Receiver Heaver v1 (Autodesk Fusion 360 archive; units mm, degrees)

design "Receiver Heaver" references "91855A480_18-8 STAINLESS STEEL CAP NUT", "90107A029_TYPE 316 STAINLESS STEEL FLAT WASHER (1)", "95412A736_18-8 STAINLESS STEEL THREADED ROD", "92141A033_TYPE 18-8 STAINLESS STEEL FLAT WASHER", "90876A450_STEEL AND IRON WING NUTS", "6079K140_STEEL KNURLED-RIM KNOB", "91855A520_18-8 STAINLESS STEEL CAP NUT"
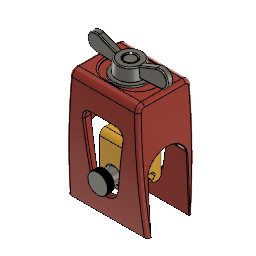
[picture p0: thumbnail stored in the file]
sketch "1913 Profile" plane through (0, 0, 0) normal (1, 0, 0) x axis (0, 1, 0)
  line L1 (-8.2514, 0) -> (-1.27, 0)
  line L2 (-10.5764, -2.2198) -> (-8.431, -0.0744)
  line L3 (-10.6426, -3.9497) -> (-10.6426, -2.286)
  line L4 (-8.0759, -6.5164) -> (-10.5764, -4.0159)
  line L5 (-7.874, -6.7193) -> (-7.874, -6.7183)
  line L6 (-12.6963, -9.2603) -> (-10.413, -9.2593)
  line L7 (-9.7763, 28.3845) -> (-9.7763, 16.5028)
  line L8 (0, 28.6385) -> (-9.5223, 28.6385)
  line L9 (0, 34.9885) -> (0, 28.6385)
  line L10 (-11.4416, 34.9885) -> (0, 34.9885)
  line L11 (-16.5079, -5.4518) -> (-16.5216, 29.9065)
  line L12 (-0.635, 6.9855) -> (-0.635, 0.635)
  line L13 (11.4417, 34.9885) -> (0, 34.9885)
  line L14 (16.508, -5.4518) -> (16.5217, 29.9065)
  line L15 (12.6964, -9.2603) -> (10.413, -9.2593)
  line L16 (8.076, -6.5164) -> (10.5765, -4.0159)
  line L17 (10.5765, -2.2198) -> (8.4311, -0.0744)
  line L18 (8.2515, 0) -> (1.2701, 0)
  line L19 (0.6351, 6.9855) -> (0.6351, 0.635)
  line L20 (9.7764, 28.3845) -> (9.7764, 16.5028)
  line L21 (0, 28.6385) -> (9.5224, 28.6385)
  arc A1 centre (-0.8863, 16.5028) radius 8.89 clockwise from (-1.2444, 7.62) to (-9.7763, 16.5028)
  arc A2 centre (-9.5223, 28.3845) radius 0.254 clockwise from (-9.7763, 28.3845) to (-9.5223, 28.6385)
  arc A3 centre (-10.414, -6.7193) radius 2.54 clockwise from (-7.8953, -7.0474) to (-10.413, -9.2593)
  arc A4 centre (-8.525, -6.9654) radius 0.635 clockwise from (-8.0759, -6.5164) to (-7.8953, -7.0474)
  arc A5 centre (-9.6784, -3.1179) radius 1.27 clockwise from (-10.5764, -4.0159) to (-10.5764, -2.2198)
  arc A6 centre (-1.27, 0.635) radius 0.635 clockwise from (-0.635, 0.635) to (-1.27, 0)
  arc A7 centre (-12.6979, -5.4503) radius 3.81 clockwise from (-12.6963, -9.2603) to (-16.5079, -5.4518)
  arc A8 centre (-11.4416, 29.9085) radius 5.08 clockwise from (-16.5216, 29.9065) to (-11.4416, 34.9885)
  arc A9 centre (-8.2514, -0.254) radius 0.254 clockwise from (-8.431, -0.0744) to (-8.2514, 0)
  arc A10 centre (-1.27, 6.9855) radius 0.635 clockwise from (-1.2444, 7.62) to (-0.635, 6.9855)
  arc A11 centre (11.4417, 29.9085) radius 5.08 clockwise from (11.4417, 34.9885) to (16.5217, 29.9065)
  arc A12 centre (12.698, -5.4503) radius 3.81 clockwise from (16.508, -5.4518) to (12.6964, -9.2603)
  arc A13 centre (10.4141, -6.7193) radius 2.54 clockwise from (10.413, -9.2593) to (7.8953, -7.0474)
  arc A14 centre (8.525, -6.9654) radius 0.635 clockwise from (7.8953, -7.0474) to (8.076, -6.5164)
  arc A15 centre (9.6785, -3.1179) radius 1.27 clockwise from (10.5765, -2.2198) to (10.5765, -4.0159)
  arc A16 centre (8.2515, -0.254) radius 0.254 clockwise from (8.2515, 0) to (8.4311, -0.0744)
  arc A17 centre (1.2701, 0.635) radius 0.635 clockwise from (1.2701, 0) to (0.6351, 0.635)
  arc A18 centre (1.2701, 6.9855) radius 0.635 clockwise from (0.6351, 6.9855) to (1.2445, 7.62)
  arc A19 centre (0.8864, 16.5028) radius 8.89 clockwise from (9.7764, 16.5028) to (1.2445, 7.62)
  arc A20 centre (9.5224, 28.3845) radius 0.254 clockwise from (9.5224, 28.6385) to (9.7764, 28.3845)
  point P8 (-9.7763, 9.525)
  point P5 (-7.874, -9.2583)
  point P7 (-9.2583, -5.334)
  point P6 (-9.4996, -1.143)
  point P2 (-10.6426, -2.286)
  point P3 (-10.6426, -3.9497)
  point P17 (-1.0952, 0)
  point P13 (-11.4427, 34.9885)
  point P9 (0, 28.6385)
  point P70 (0, 28.6385)
  point P10 (-9.7763, 16.5028)
  point P67 (9.7764, 16.5028)
  point P12 (0, 34.9885)
  point P42 (0, 34.9885)
  point P14 (-9.5223, 28.6385)
  point P69 (9.5224, 28.6385)
  point P15 (-9.7763, 28.3845)
  point P68 (9.7764, 28.3845)
  point P18 (-10.413, -9.2593)
  point P49 (10.413, -9.2593)
  point P21 (-8.0759, -6.5164)
  point P53 (8.076, -6.5164)
  point P22 (-7.8953, -7.0474)
  point P51 (7.8953, -7.0474)
  point P24 (-10.5764, -2.2198)
  point P56 (10.5765, -2.2198)
  point P25 (-10.5764, -4.0159)
  point P54 (10.5765, -4.0159)
  point P27 (-1.27, 0)
  point P60 (1.2701, 0)
  point P28 (-0.635, 0.635)
  point P62 (0.6351, 0.635)
  point P30 (-16.5079, -5.4518)
  point P46 (16.508, -5.4518)
  point P31 (-12.6963, -9.2603)
  point P48 (12.6964, -9.2603)
  point P33 (-11.4416, 34.9885)
  point P43 (11.4417, 34.9885)
  point P34 (-16.5216, 29.9065)
  point P45 (16.5217, 29.9065)
  point P36 (-8.2514, 0)
  point P59 (8.2515, 0)
  point P37 (-8.431, -0.0744)
  point P57 (8.4311, -0.0744)
  point P39 (-0.635, 6.9855)
  point P63 (0.6351, 6.9855)
  point P40 (-1.2444, 7.62)
  point P65 (1.2445, 7.62)
  point P1 (0, 0)
  point P4 (-7.874, -6.7183)
  horizontal L1
  vertical L3
  parallel L3 L5
  perpendicular L7 L8
  coincident P8 L7
  tangent L7 A1
  perpendicular L8 L9
  perpendicular L9 L10
  tangent L8 A2
  tangent L7 A2
  coincident P5 L6
  coincident P5 L5
  tangent L6 A3
  tangent L5 A3
  coincident L4 P7
  tangent L4 A4
  tangent A3 A4
  coincident L2 P6
  coincident P2 L2
  coincident P3 L4
  tangent L2 A5
  tangent L4 A5
  coincident L1 P17
  tangent L1 A6
  tangent L11 A7
  tangent L6 A7
  coincident L10 P13
  tangent L10 A8
  tangent L11 A8
  tangent L1 A9
  tangent L2 A9
  vertical L12
  tangent A1 A10
  tangent L12 A10
  symmetric P9 L9 P70
  symmetric P10 L9 P67
  symmetric A1 L9 A19
  symmetric P12 L9 P42
  symmetric L9 P14 P69
  symmetric L9 P15 P68
  symmetric L9 A2 A20
  symmetric L9 P18 P49
  symmetric L9 A3 A13
  symmetric L9 P21 P53
  symmetric L9 P22 P51
  symmetric L9 A4 A14
  symmetric L9 P24 P56
  symmetric L9 P25 P54
  symmetric L9 A5 A15
  symmetric L9 P27 P60
  symmetric L9 P28 P62
  symmetric L9 A6 A17
  symmetric L9 P30 P46
  symmetric L9 P31 P48
  symmetric L9 A7 A12
  symmetric L9 P33 P43
  symmetric L9 P34 P45
  symmetric L9 A8 A11
  symmetric L9 P36 P59
  symmetric L9 P37 P57
  symmetric L9 A9 A16
  symmetric L9 P39 P63
  symmetric L9 P40 P65
  symmetric L9 A10 A18
  dimension "d9" distance P1 L3 = 10.6426 (= "( 0.838 / 2 ) * 1 in")
  dimension "d10" angle L2 L3 = 135
  dimension "d11" angle L3 L4 = 135
  dimension "d12" distance P1 L5 = 7.874 (= "( 0.620 / 2 ) * 1 in")
  dimension "d13" distance P6 P7 = 4.191
  dimension "d14" distance P1 P6 = 9.4996 (= "( 0.748 / 2 ) * 1 in")
  dimension "d15" distance P4 P5 = 2.54
  dimension "d20" radius A1 = 8.89
  dimension "d21" distance P9 P12 = 6.35
  dimension "d23" radius A2 = 0.254
  dimension "d30" radius A4 = 0.635
  dimension "d31" radius A5 = 1.27
  dimension "d32" radius A6 = 0.635
  dimension "d34" distance P12 P13 = 11.4427
  dimension "d36" distance P1 L11 = 16.51 (= "( 1.3 / 2 ) * 1 in")
  dimension "d37" radius A7 = 3.81
  dimension "d38" radius A8 = 5.08
  dimension "d39" radius A9 = 0.254
  dimension "d40" radius A10 = 0.635
  dimension "d41" distance P1 L12 = 0.635
  dimension "d50" distance L1 P40 = 7.62
  dimension "d51" distance L8 P40 = 21.0185 (= "( 13 / 16 ) * 1 in + 0.015 in")
canvas "Canvas1"
extrude "Extrude1" new body sketch "1913 Profile" profile of L1 L2 L4 L6 L7 L8 A1 L9 L10 A2 A3 A4 A5 A6 L11 A7 A8 A9 L12 A10 L13 A11 L14 A12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 distance 12.7 bodies "1913 Adapter"
sketch "1913 Top Holes" plane through (0, 0, 34.9885) normal (0, 0, 1) x axis (-1, 0, 0)
  line L1 (-12.7, 11.4416) -> (12.7, 11.4416)
  line L2 (-12.7, -11.4417) -> (-12.7, 11.4416)
  line L3 (12.7, -11.4417) -> (-12.7, -11.4417)
  line L4 (12.7, 11.4416) -> (12.7, -11.4417)
  circle C1 centre (0, 0) radius 6.7945
  circle C2 centre (0, 0) radius 13.97
  point P1 (0, 0)
  point P6 (0, 0)
  point P7 (0, 0)
  coincident P1 P6
  coincident P1 P7
  dimension "d44" diameter C1 = 13.589
  dimension "d45" diameter C2 = 27.94
extrude "Extrude2" cut sketch "1913 Top Holes" profile of C1 against normal blind 16.51
sketch "Through hole for 1913" plane through (0, -0.635, 0) normal (0, 1, 0) x axis (-1, 0, 0)
  line L1 (-12.7, 6.9855) -> (12.7, 6.9855)
  line L2 (-12.7, 0.635) -> (-12.7, 6.9855)
  line L3 (12.7, 0.635) -> (-12.7, 0.635)
  line L4 (12.7, 6.9855) -> (12.7, 0.635)
  circle C1 centre (0, 3.81) radius 3.6195
  dimension "d52" diameter C1 = 7.239
extrude "Extrude4" cut sketch "Through hole for 1913" profile of L1 L3 C1 distance 50.8
sketch "Sketch7" plane through (0, -16.51, -0.0064) normal (0, -1, -0.0004) x axis (1, 0, 0)
  line L1 (12.7, -5.4454) -> (-12.7, -5.4454)
  line L2 (12.7, 29.9129) -> (12.7, -5.4454)
  line L3 (-12.7, 29.9129) -> (12.7, 29.9129)
  line L4 (-12.7, -5.4454) -> (-12.7, 29.9129)
  closed curve K1 centre (0, 3.8164)
  circle C1 centre (0, 3.8164) radius 8.0645
  concentric K1 C1
  dimension "d55" diameter C1 = 16.129
extrude "Extrude6" cut sketch "Sketch7" profile of K1 C1 against normal blind 2.54
extrude "Extrude5" cut sketch "Sketch7" profile of K1 C1 against normal blind 1.27
sketch "Through hole nut" plane through (0, 16.5101, -0.0064) normal (0, 1, -0.0004) x axis (-1, 0, 0)
  line L1 (-12.7, 29.9129) -> (12.7, 29.9129)
  line L2 (-12.7, -5.4454) -> (-12.7, 29.9129)
  line L3 (12.7, -5.4454) -> (-12.7, -5.4454)
  line L4 (12.7, 29.9129) -> (12.7, -5.4454)
  line L5 (-6.5625, 3.81) -> (-3.2812, 9.4932)
  line L6 (-3.2812, -1.8733) -> (-6.5625, 3.81)
  line L7 (3.2812, -1.8733) -> (-3.2812, -1.8733)
  line L8 (6.5625, 3.81) -> (3.2812, -1.8733)
  line L9 (3.2812, 9.4932) -> (6.5625, 3.81)
  line L10 (-3.2812, 9.4932) -> (3.2812, 9.4932)
  point P6 (0, 3.81)
  point P7 (0, 3.81)
  point P14 (0, 3.81)
  coincident P6 P7
  coincident P7 P14
  dimension "d87" distance P14 L10 = 5.6832 (= "( ( 7 / 16 / 2 ) + 0.005 ) * 1 in")
extrude "Extrude8" cut sketch "Through hole nut" profile of L5 L6 L7 L8 L9 L10 against normal blind 3.7703 (magnitude of "( -19 / 32 / 4 ) * 1 in")
component_insert "Component Insert2"
joint "Assemble3" OffsetX 0 OffsetY 0 OffsetZ 0 AngleZ 0 alignAngle 0 alignOffsetX 0 alignOffsetY 0 alignOffsetZ 0
component_insert "Component Insert3"
joint "Assemble4" OffsetX 0 OffsetY 0 OffsetZ 0 AngleZ 0 OffsetX 0 OffsetY 0 OffsetZ 0 AngleZ 0 alignAngle 0 alignOffsetX 0 alignOffsetY 0 alignOffsetZ 0
component_insert "Component Insert4"
joint "Assemble5" OffsetX 0 OffsetY 0 OffsetZ 0 AngleZ 0 alignAngle -30 alignOffsetX 0 alignOffsetY 0 alignOffsetZ 0
component_insert "Component Insert6"
joint "Assemble6" OffsetX 0 OffsetY 0 OffsetZ 0 AngleZ 0 alignAngle -30 alignOffsetX 0 alignOffsetY 0 alignOffsetZ 0
component_insert "Component Insert7"
joint "Assemble7" OffsetX 0 OffsetY 0 OffsetZ 0 AngleZ 0 OffsetX 0 OffsetY 0 OffsetZ 0 AngleZ 0 alignAngle 180 alignOffsetX 0 alignOffsetY 0 alignOffsetZ 0
component_insert "Component Insert8"
component_insert "Component Insert9"
component_from_bodies "Body->Comp1"
sketch "Major part" plane through (0, 0, 0) normal (1, 0, 0) x axis (0, 1, 0)
  line L1 (-21.59, 0) -> (-17.78, 0)
  line L2 (-19.33, 107.95) -> (0, 107.95)
  line L3 (0, 95.25) -> (0, 107.95)
  line L4 (-2.941, 95.25) -> (0, 95.25)
  line L5 (19.33, 107.95) -> (0, 107.95)
  line L6 (21.59, 0) -> (17.78, 0)
  line L7 (2.941, 95.25) -> (0, 95.25)
  circle C1 centre (0, 0) radius 17.145
  arc A1 centre (608.8529, 76.2932) radius 635.0425 clockwise from (-21.59, 0) to (-25.6748, 101.8556)
  arc A2 centre (3834.7614, 59.3271) radius 3852.9981 clockwise from (-17.78, 0) to (-18.1808, 80.0921)
  arc A3 centre (-2.941, 80.01) radius 15.24 clockwise from (-18.1808, 80.0921) to (-2.941, 95.25)
  arc A4 centre (-19.33, 101.6) radius 6.35 clockwise from (-25.6748, 101.8556) to (-19.33, 107.95)
  arc A5 centre (19.33, 101.6) radius 6.35 clockwise from (19.33, 107.95) to (25.6748, 101.8556)
  arc A6 centre (-608.8529, 76.2932) radius 635.0425 clockwise from (25.6748, 101.8556) to (21.59, 0)
  arc A7 centre (-3834.7614, 59.3271) radius 3852.9981 clockwise from (18.1808, 80.0921) to (17.78, 0)
  arc A8 centre (2.941, 80.01) radius 15.24 clockwise from (2.941, 95.25) to (18.1808, 80.0921)
  point P1 (0, 0)
  point P2 (0, 0)
  point P6 (-25.4, 107.95)
  point P3 (-17.78, 0)
  point P24 (17.78, 0)
  point P4 (-21.59, 0)
  point P21 (21.59, 0)
  point P5 (0, 107.95)
  point P16 (0, 107.95)
  point P9 (0, 95.25)
  point P27 (0, 95.25)
  point P10 (-2.941, 95.25)
  point P26 (2.941, 95.25)
  point P11 (-18.1808, 80.0921)
  point P23 (18.1808, 80.0921)
  point P13 (-19.33, 107.95)
  point P17 (19.33, 107.95)
  point P14 (-25.6748, 101.8556)
  point P19 (25.6748, 101.8556)
  coincident P1 P2
  horizontal L1
  horizontal L2
  perpendicular L2 L3
  perpendicular L3 L4
  tangent A2 A3
  tangent L4 A3
  coincident P6 L2
  coincident P6 A1
  tangent A1 A4
  tangent L2 A4
  symmetric P3 L3 P24
  symmetric P4 L3 P21
  symmetric P5 L3 P16
  symmetric A1 L3 A6
  symmetric A2 L3 A7
  symmetric P9 L3 P27
  symmetric L3 P10 P26
  symmetric L3 P11 P23
  symmetric L3 A3 A8
  symmetric L3 P13 P17
  symmetric L3 P14 P19
  symmetric L3 A4 A5
  dimension "d162" diameter C1 = 34.29
  dimension "d163" distance P3 P4 = 3.81
  dimension "d164" distance P2 P3 = 17.78 (= "( 1.4 / 2 ) * 1 in")
  dimension "d165" distance P5 P6 = 25.4
  dimension "d166" distance P1 L2 = 107.95
  dimension "d167" distance P5 P9 = 12.7
  dimension "d168" radius A3 = 15.24
  dimension "d169" radius A4 = 6.35
position "Position2"
extrude "Extrude9" new body sketch "Major part" profile of L1 L2 A1 A2 L3 L4 A3 A4 L5 A5 A6 A7 A8 L6 L7 distance 38.1
sketch "Cutout in major" plane through (0, 0, 0) normal (0, 1, 0) x axis (1, 0, 0)
  line L1 (0, -17.78) -> (0, -22.86)
  line L2 (0, -40.64) -> (0, -17.78)
  line L3 (0, -81.28) -> (0, -40.64)
  line L4 (-11.7427, -81.28) -> (0, -81.28)
  line L5 (-12.7, -17.78) -> (0, -17.78)
  line L6 (-18.0306, -74.0441) -> (-11.6955, -29.0772)
  line L7 (11.7427, -81.28) -> (0, -81.28)
  line L8 (18.0306, -74.0441) -> (11.6955, -29.0772)
  arc A1 centre (-11.7427, -74.93) radius 6.35 clockwise from (-11.7427, -81.28) to (-18.0306, -74.0441)
  arc A2 centre (11.7427, -74.93) radius 6.35 clockwise from (18.0306, -74.0441) to (11.7427, -81.28)
  arc A3 centre (0, -30.7249) radius 11.811 clockwise from (-11.6955, -29.0772) to (11.6955, -29.0772)
  point P6 (-19.05, -81.28)
  point P7 (-10.9985, -24.13)
  point P5 (0, -81.28)
  point P12 (0, -81.28)
  point P9 (-11.7427, -81.28)
  point P13 (11.7427, -81.28)
  point P10 (-18.0306, -74.0441)
  point P15 (18.0306, -74.0441)
  point P3 (0, -17.78)
  vertical L1
  parallel L1 L2
  parallel L2 L3
  perpendicular L3 L4
  horizontal L5
  coincident P6 L4
  coincident P6 L6
  tangent L4 A1
  tangent L6 A1
  coincident P7 L6
  symmetric P5 L3 P12
  symmetric L3 P9 P13
  symmetric L3 P10 P15
  symmetric L3 A1 A2
  tangent L6 A3
  tangent L8 A3
  dimension "d172" distance P5 P6 = 19.05
  dimension "d174" distance P3 P7 = 12.7
  dimension "d175" radius A1 = 6.35
  dimension "d178" radius A3 = 11.811
extrude "Extrude10" cut sketch "Cutout in major" profile of L1 L2 L3 L4 L6 A1 L7 A2 L8 A3 distance 50.8
sketch "Washer recess in major" plane through (0, 0, 107.95) normal (0, 0, 1) x axis (-1, 0, 0)
  line L1 (-38.1, 19.33) -> (38.1, 19.33)
  line L2 (-38.1, -19.33) -> (-38.1, 19.33)
  line L3 (38.1, -19.33) -> (-38.1, -19.33)
  line L4 (38.1, 19.33) -> (38.1, -19.33)
  line L5 (-6.35, 17.145) -> (6.35, 17.145)
  line L6 (6.35, -17.145) -> (-6.35, -17.145)
  line L7 (-6.35, 0) -> (6.35, 0)
  arc A1 centre (-6.35, 0) radius 17.145 clockwise from (-6.35, -17.145) to (-6.35, 17.145)
  arc A2 centre (6.35, 0) radius 17.145 clockwise from (6.35, 17.145) to (6.35, -17.145)
  tangent L5 A1
  tangent A1 L6
  parallel L5 L6
  tangent L6 A2
  tangent L5 A2
  horizontal L7
  dimension "d186" diameter A1 = 34.29
extrude "Extrude11" cut sketch "Washer recess in major" profile of L5 A1 L6 A2 against normal blind 1.905
fillet "Fillet1" radius 0.127
fillet "Fillet2" radius 1.27
sketch "Sketch14" plane through (0, 0, 106.045) normal (0, 0, 1) x axis (-1, 0, 0)
  line L1 (-6.35, 17.018) -> (6.35, 17.018)
  line L2 (6.35, -17.018) -> (-6.35, -17.018)
  arc A1 centre (-6.35, 0) radius 17.018 clockwise from (-6.35, -17.018) to (-6.35, 17.018)
  arc A2 centre (6.35, 0) radius 17.018 clockwise from (6.35, 17.018) to (6.35, -17.018)
  circle C1 centre (0, -0.0109) radius 6.7945
extrude "Extrude12" cut sketch "Sketch14" profile of C1 against normal blind 13.97
sketch "Sketch15" plane through (38.1, 0, 0) normal (1, 0, 0) x axis (0, 1, 0)
  line L1 (2.941, 95.25) -> (-2.941, 95.25)
  line L2 (21.59, 0) -> (17.78, 0)
  line L3 (-19.33, 107.95) -> (19.33, 107.95)
  line L4 (-17.78, 0) -> (-21.59, 0)
  line L5 (-0.0226, 63.5) -> (0, 50.8)
  line L6 (-23.679, 19.8819) -> (-18.2273, 50.8)
  line L7 (13.1678, 50.8) -> (-18.2273, 50.8)
  line L8 (23.789, 19.9663) -> (18.2272, 50.8649)
  arc A1 centre (2.941, 80.01) radius 15.24 clockwise from (2.941, 95.25) to (18.1808, 80.0921)
  arc A2 centre (-3834.7614, 59.3271) radius 3852.9981 clockwise from (18.1808, 80.0921) to (17.78, 0)
  arc A3 centre (-608.8529, 76.2932) radius 635.0425 clockwise from (25.6748, 101.8556) to (21.59, 0)
  arc A4 centre (19.33, 101.6) radius 6.35 clockwise from (19.33, 107.95) to (25.6748, 101.8556)
  arc A5 centre (-19.33, 101.6) radius 6.35 clockwise from (-25.6748, 101.8556) to (-19.33, 107.95)
  arc A6 centre (608.8529, 76.2932) radius 635.0425 clockwise from (-21.59, 0) to (-25.6748, 101.8556)
  arc A7 centre (3834.7614, 59.3271) radius 3852.9981 clockwise from (-17.78, 0) to (-18.1808, 80.0921)
  arc A8 centre (-2.941, 80.01) radius 15.24 clockwise from (-18.1808, 80.0921) to (-2.941, 95.25)
  arc A9 centre (-0.8362, 45.2685) radius 18.2496 clockwise from (-18.2273, 50.8) to (-0.0226, 63.5)
  arc A10 centre (0.8559, 45.2715) radius 18.2496 clockwise from (-0.0226, 63.5) to (18.2272, 50.8649)
  point P23 (-18.2273, 50.8)
  point P28 (18.2272, 50.8649)
  point P24 (-0.0226, 63.5)
  point P27 (-0.0226, 63.5)
  point P29 (-23.679, 19.8819)
  point P31 (18.2272, 50.8649)
  point P32 (23.789, 19.9663)
  coincident A7 P23
  symmetric P23 L5 P28
  symmetric P24 L5 P27
  symmetric L5 A9 A10
  horizontal L7
  coincident A6 P29
  symmetric P23 L5 P31
  symmetric L5 P29 P32
  dimension "d195" angle L6 L7 = 100
extrude "Extrude13" new body sketch "Sketch15" profile of L1 A1 A2 A3 A4 L3 A5 A6 A7 A8 A9 A10 L6 L8 against normal blind 12.7
copy_paste_bodies "CopyPasteBodies1"
move "Move1"
combine "Combine1"
draft "Draft1" Angle1 3 Angle2 0
draft "Draft2" Angle1 3 Angle2 0
fillet "Fillet3" radius 3.175
fillet "Fillet4" radius 3.175
fillet "Fillet5" radius 1.27
fillet "Fillet6" radius 1.27
fillet "Fillet7" radius 1.27
fillet "Fillet8" radius 1.27
fillet "Fillet9" radius 0.635
fillet "Fillet10" radius 0.635
fillet "Fillet11" radius 1.27
fillet "Fillet12" radius 1.27
joint "Assemble8" OffsetX 0 OffsetY 0 OffsetZ 0 AngleZ 0 alignAngle 0 alignOffsetX 0 alignOffsetY 0 alignOffsetZ 0
joint "Assemble9" OffsetX 0 OffsetY 0 OffsetZ 0 AngleZ 0 OffsetX 0 OffsetY 0 OffsetZ 0 AngleZ 0 alignAngle 180 alignOffsetX 0 alignOffsetY 0 alignOffsetZ 0
component_from_bodies "Body->Comp2"
fillet "Fillet1" radius 0.635
fillet "Fillet2" radius 0.635
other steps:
base_feature "Base Feature1" bodies "Major"
base_feature "Base Feature1" bodies "1913 Adapter"
base_feature "Base Feature1"
joint_origin "JointOrigin3" OffsetX 0 OffsetY 0 OffsetZ 0 AngleZ 0
joint_origin "JointOrigin4" OffsetX 0 OffsetY 0 OffsetZ 0 AngleZ 0
joint_origin "JointOrigin5" OffsetX 0 OffsetY 0 OffsetZ 0 AngleZ 0
create_component "CreateComponent1"
remove_body "RemoveBody1"
joint_origin "JointOrigin6" OffsetX 0 OffsetY 0 OffsetZ 0 AngleZ 0
create_component "CreateComponent2"
remove_body "RemoveBody2"
named bodies: "1913 Adapter", "Major"

design "90876A450_STEEL AND IRON WING NUTS"
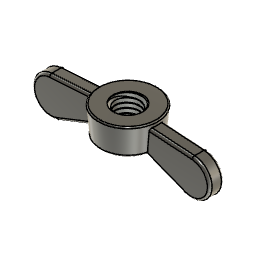
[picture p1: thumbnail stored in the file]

design "6079K140_STEEL KNURLED-RIM KNOB"
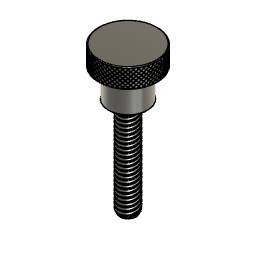
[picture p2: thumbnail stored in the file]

design "91855A520_18-8 STAINLESS STEEL CAP NUT"
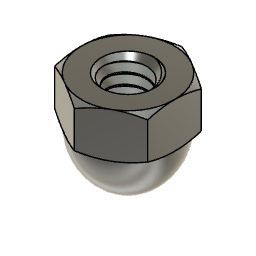
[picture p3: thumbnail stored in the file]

design "90107A029_TYPE 316 STAINLESS STEEL FLAT WASHER (1)"
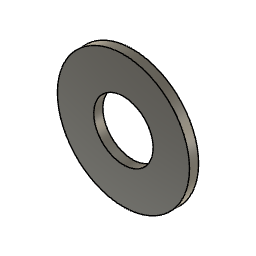
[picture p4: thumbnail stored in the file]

design "95412A736_18-8 STAINLESS STEEL THREADED ROD"
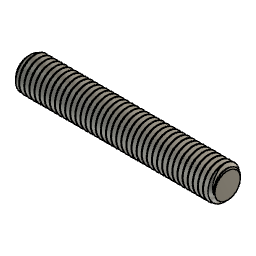
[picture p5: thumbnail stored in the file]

design "91855A480_18-8 STAINLESS STEEL CAP NUT"
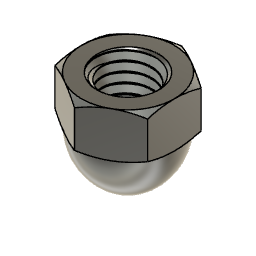
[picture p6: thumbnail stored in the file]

design "92141A033_TYPE 18-8 STAINLESS STEEL FLAT WASHER"
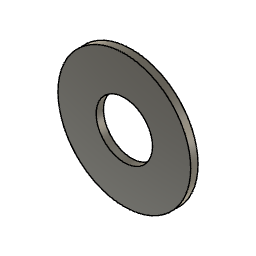
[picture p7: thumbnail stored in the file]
